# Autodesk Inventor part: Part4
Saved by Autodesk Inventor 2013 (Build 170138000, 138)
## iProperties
Created: 2012-07
Part Number: Part4
Material: Generic
Document SubType Name: Modeling
Designer: Paul
Density: 1 g/cm^3
Author: Paul
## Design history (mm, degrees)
node "User Library-Arduino Mega.SAT1"
body "Solid1"
node "Base1"
